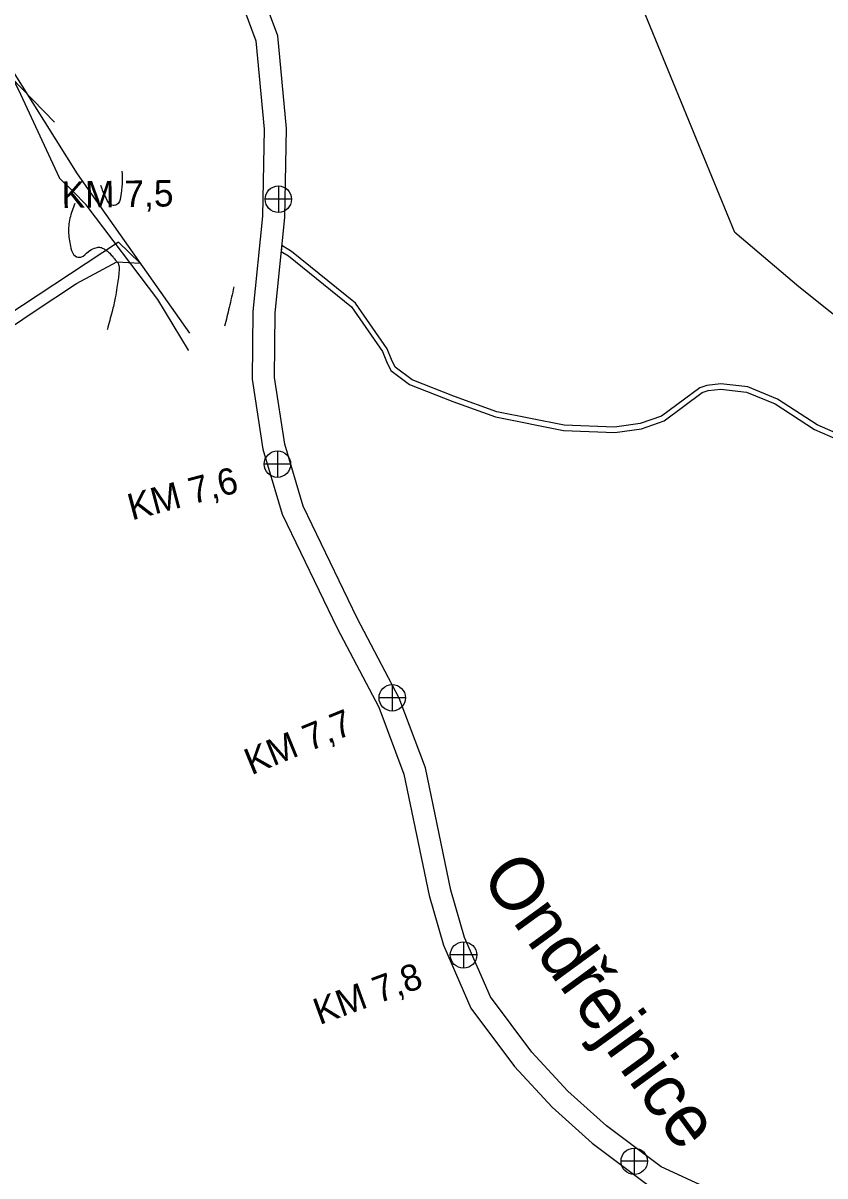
# Model space of a CAD drawing. Extents: x -478464 to -472469, y -1118040 to -1113785.
# Drawn here: x -476660 to -476356.8, y -1116160 to -1115724 of the extents above; entities that cross this region are included whole.
import ezdxf

# ---------------------------------------------------------------- set-up
doc = ezdxf.new("R2010")
doc.units = 0
for name, color, linetype in [('el vedeni_NN', 7, 'Continuous'), ('ObPÚ', 7, 'Continuous'), ('silnice', 7, 'Continuous'), ('staničení toku', 7, 'Continuous'), ('VAK_kanalizace', 7, 'Continuous'), ('VAK_vodovod', 7, 'Continuous'), ('vodní plochy', 7, 'Continuous'), ('Vrstevnice_vedlejsi', 7, 'Continuous')]:
    doc.layers.add(name, color=color, linetype=linetype)

msp = doc.modelspace()

# ---------------------------------------------------------------- linework, layer by layer
at = {"layer": 'el vedeni_NN'}
msp.add_lwpolyline([(-476752.574, -1115649.093), (-476730.57, -1115674.25), (-476705.81, -1115701.99), (-476648.091, -1115761.403)], dxfattribs=at)
at = {"layer": 'ObPÚ'}
msp.add_lwpolyline([(-476672.35, -1115844.14), (-476656.16, -1115833.32), (-476639.83, -1115822.49), (-476624.61, -1115814.28), (-476615.68, -1115814.82), (-476623.99, -1115806.81), (-476672.64, -1115838.9)], dxfattribs=at)
at = {"layer": 'silnice'}
msp.add_lwpolyline([(-476261.922, -1115907.288), (-476366.595, -1115823.727), (-476390.845, -1115803.24), (-476425.665, -1115718.481), (-476494.983, -1115557.356), (-476524.795, -1115496.42), (-476580.823, -1115418.032), (-476641.911, -1115352.297), (-476741.891, -1115268.259), (-476824.194, -1115202.313), (-477005.33, -1115056.573), (-477039.82, -1115023.276), (-477040.729, -1115022.048)], dxfattribs=at)
at = {"layer": 'staničení toku'}
for p, q in [((-476563.491, -1115785.588), (-476563.491, -1115795.588)), ((-476558.491, -1115790.588), (-476568.491, -1115790.588)), ((-476563.839, -1115885.795), (-476563.839, -1115895.795)), ((-476558.839, -1115890.795), (-476568.839, -1115890.795)), ((-476520.422, -1115974.182), (-476520.422, -1115984.182)), ((-476515.422, -1115979.182), (-476525.422, -1115979.182)), ((-476493.455, -1116071.473), (-476493.455, -1116081.473)), ((-476488.455, -1116076.473), (-476498.455, -1116076.473)), ((-476428.891, -1116149.502), (-476428.891, -1116159.502)), ((-476423.891, -1116154.502), (-476433.891, -1116154.502))]:
    msp.add_line(p, q, dxfattribs=at)
for centre in [(-476563.491, -1115790.588), (-476563.839, -1115890.795), (-476520.422, -1115979.182), (-476493.455, -1116076.473), (-476428.891, -1116154.502)]:
    msp.add_circle(centre, 5, dxfattribs=at)
at = {"layer": 'VAK_kanalizace'}
msp.add_lwpolyline([(-476596.91, -1115841.27), (-476639.491, -1115781.004), (-476677.085, -1115721.078), (-476807.031, -1115538.469)], dxfattribs=at)
at = {"layer": 'VAK_vodovod'}
msp.add_lwpolyline([(-476597.42, -1115847.819), (-476597.5, -1115847.629), (-476609.099, -1115828.549), (-476636.19, -1115792.68), (-476641.09, -1115787.7), (-476646.199, -1115782.6), (-476646.3, -1115782.469), (-476660.829, -1115750.93), (-476672.039, -1115728.579), (-476672.619, -1115727.94), (-476672.81, -1115728.211), (-476672.829, -1115728.19)], dxfattribs=at)
at = {"layer": 'vodní plochy'}
for points in [[(-476388.083, -1116170.718), (-476418.752, -1116156.59), (-476439.429, -1116141.074), (-476454.001, -1116128.018), (-476467.661, -1116113.266), (-476483.308, -1116092.249), (-476493.091, -1116069.906), (-476498.268, -1116051.992), (-476507.828, -1116005.719), (-476517.743, -1115979.265), (-476533.743, -1115949.077), (-476554.161, -1115906.714), (-476561.038, -1115883.278), (-476564.915, -1115858.06), (-476564.699, -1115833.581), (-476561.088, -1115797.453), (-476560.393, -1115763.843), (-476563.707, -1115728.784), (-476571.729, -1115707.14)], [(-476579.484, -1115710.554), (-476572.024, -1115730.684), (-476568.86, -1115764.155), (-476569.538, -1115796.945), (-476573.154, -1115833.122), (-476573.38, -1115858.669), (-476569.313, -1115885.12), (-476562.082, -1115909.761), (-476541.293, -1115952.896), (-476525.473, -1115982.744), (-476515.979, -1116008.073), (-476506.486, -1116054.025), (-476501.063, -1116072.79), (-476490.67, -1116096.526), (-476474.175, -1116118.681), (-476459.94, -1116134.054), (-476444.8, -1116147.619), (-476423.109, -1116163.897)], [(-476562.153, -1115808.116), (-476562.374, -1115810.325)], [(-476348.566, -1115880.855), (-476359.748, -1115875.946), (-476374.7, -1115866.253), (-476385.987, -1115861.598), (-476396.202, -1115860.463), (-476401.399, -1115861.04), (-476404.141, -1115861.955), (-476418.569, -1115872.634), (-476426.604, -1115875.438), (-476436.381, -1115876.795), (-476455.437, -1115876.089), (-476480.838, -1115871.03), (-476496.81, -1115865.279), (-476512.863, -1115858.975), (-476519.325, -1115854.074), (-476520.706, -1115851.228), (-476522.326, -1115847.179), (-476534.326, -1115829.902), (-476558.535, -1115810.328), (-476562.153, -1115808.116)], [(-476562.374, -1115810.325), (-476559.691, -1115811.966), (-476535.806, -1115831.278), (-476524.098, -1115848.133), (-476522.536, -1115852.038), (-476520.915, -1115855.378), (-476513.851, -1115860.735), (-476497.514, -1115867.151), (-476481.376, -1115872.962), (-476455.671, -1115878.081), (-476436.279, -1115878.801), (-476426.132, -1115877.392), (-476417.623, -1115874.422), (-476403.207, -1115863.751), (-476400.967, -1115863.004), (-476396.202, -1115862.475), (-476386.489, -1115863.554), (-476375.634, -1115868.031), (-476360.7, -1115877.712), (-476349.186, -1115882.767)]]:
    msp.add_lwpolyline(points, dxfattribs=at)
at = {"layer": 'Vrstevnice_vedlejsi'}
for points in [[(-476622.638, -1115780.009), (-476623.141, -1115789.774), (-476624.635, -1115792.699), (-476626.462, -1115792.844), (-476628.623, -1115790.21), (-476630.624, -1115785.45)], [(-476640.507, -1115792.185), (-476642.3, -1115797.796), (-476642.815, -1115803.556), (-476641.902, -1115809.088), (-476640.346, -1115812.068), (-476638.148, -1115812.495), (-476635.307, -1115810.369), (-476632.96, -1115809.116), (-476631.104, -1115808.736), (-476629.742, -1115809.229), (-476628.456, -1115810.003), (-476627.246, -1115811.058), (-476626.112, -1115812.395), (-476625.203, -1115813.465), (-476624.518, -1115814.271), (-476624.058, -1115814.81), (-476623.783, -1115815.699), (-476623.692, -1115816.938), (-476623.787, -1115818.526), (-476624.063, -1115820.877), (-476624.52, -1115823.989)], [(-476624.52, -1115823.989), (-476625.159, -1115827.863), (-476626.37, -1115833.124), (-476628.153, -1115839.773), (-476628.176, -1115839.857)], [(-476580.293, -1115823.794), (-476582.083, -1115831.535), (-476583.79, -1115838.593)]]:
    msp.add_spline(points, degree=3, dxfattribs=at)

# ---------------------------------------------------------------- texts
at = {"layer": 'staničení toku'}
for s, rotation, p in [('KM 7,5', 0.79225, (-476645.433, -1115793.895)), ('KM 7,6', 14.78476, (-476618.913, -1115912.118)), ('KM 7,7', 22.29233, (-476573.7, -1116008.528)), ('KM 7,8', 20.07661, (-476547.941, -1116103.009))]:
    msp.add_text(s, height=10, rotation=rotation, dxfattribs=at).set_placement(p)
at = {"layer": 'vodní plochy'}
msp.add_text('Ondřejnice', height=20, rotation=306.08779, dxfattribs=at).set_placement((-476487.384, -1116047.089))

doc.saveas('drawing.dxf')
